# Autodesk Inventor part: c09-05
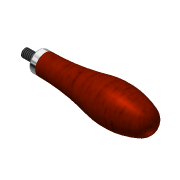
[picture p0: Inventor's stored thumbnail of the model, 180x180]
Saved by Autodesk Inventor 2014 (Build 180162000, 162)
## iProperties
Created: 2010-12
Part Number: c09-05
Document SubType Name: Modeling
Designer: Thom Tremblay
Density: 1 g/cm^3
Material: Generic
Appearance: Generic
Author: Thom Tremblay
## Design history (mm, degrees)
sketch "Sketch1"
  geometry: L1 (93.367, -68.499)-(103.527, -68.499); L2 (103.527, -68.499)-(103.527, -65.324); L3 (103.527, -65.324)-(93.367, -65.324); L4 (93.367, -65.324)-(93.367, -68.499); L5 (103.527, -68.499)-(108.607, -68.499); L6 (108.607, -68.499)-(108.607, -60.879); L7 (108.607, -60.879)-(103.527, -60.879); L8 (103.527, -60.879)-(103.527, -68.499); L9 (192.427, -68.499)-(108.607, -68.499); L10 (192.427, -68.499)-(192.427, -75.403); A1 r 177.8 centre (108.607, 116.921) between (108.607, -60.879) and (149.179, -56.188); A2 r 60.96 centre (163.089, -115.54) between (186.103, -59.091) and (149.179, -56.188); A3 r 10.16 centre (182.267, -68.499) between (192.427, -68.499) and (186.103, -59.091); 1 further point
  constraints: 20 end point, 6 point on circle, 4 parallel, 4 tangent, 3 centre point, 3 perpendicular, 2 horizontal, 1 collinear
  dimensions: "d0" = 10.16 distance of L3.end L2.end; "d1" = 3.175 distance of L2.end L1.end; "d2" = 5.08 distance of L7.end L6.end; "d3" = 7.62 distance of L6.end L5.end; "d4" = 88.9 distance between parallel lines of L10 L2; "d5" = 60.96 radius of A2; "d6" = 177.8 radius of A1; "d7" = 10.16 radius of A3
revolve "Revolution1" sketch "Sketch1" stored, may be unused: angle "d8" = 90 deg
thread "Thread1" dims "d9" = 8.89, "d10" = 0
fillet "Fillet1" dims "d11" = 1.27
body "Solid1"
